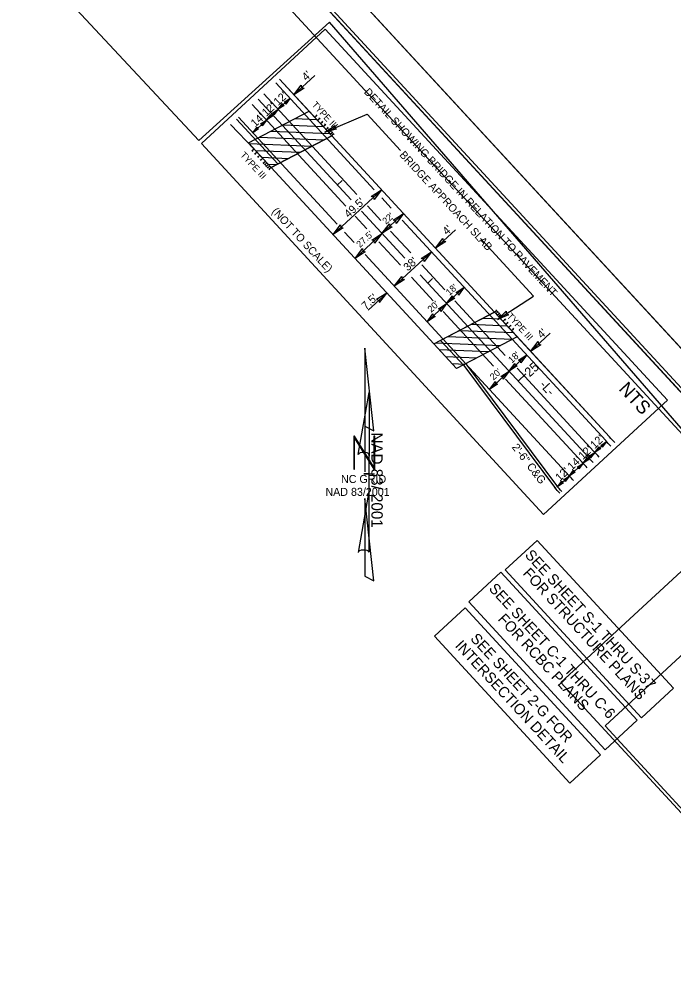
# Model space of a CAD drawing. Extents: x 1702837 to 1704783, y 793612 to 795591.
# Drawn here: x 1703998 to 1704489, y 794195 to 794914 of the extents above; entities that cross this region are included whole.
import ezdxf

# ---------------------------------------------------------------- set-up
doc = ezdxf.new("R2010")
doc.units = 0
for name, color, linetype in [('Default', 7, 'Continuous'), ('Old_Level_1', 7, 'Continuous'), ('Prop Approach Slab', 7, 'Continuous'), ('Prop Conc 2ft 6in Curb and Gutter', 7, 'Continuous'), ('Prop Dimension', 7, 'Continuous'), ('Prop Dimension Text', 7, 'Continuous'), ('Prop EOT', 7, 'Continuous'), ('Prop Guardrail', 7, 'Continuous'), ('Prop Guardrail Anchor Unit CELL', 7, 'Continuous'), ('Prop Horizontal Alignment', 7, 'Continuous'), ('Prop Horizontal Alignment Station Label', 7, 'Continuous'), ('Prop Horizontal Alignment Tick Label', 7, 'Continuous'), ('Prop Horizontal Alignment Tick Large', 7, 'Continuous'), ('Prop Horizontal Alignment Tick Small', 7, 'Continuous'), ('Prop Lane Lines', 7, 'Continuous'), ('Prop North Arrow NAD83 for Plan Sheets CELL', 7, 'Continuous'), ('Prop Paved Shoulder', 7, 'Continuous'), ('Prop Roadway Bridge', 7, 'Continuous'), ('Prop Structure Anchor Unit CELL', 7, 'Continuous'), ('Prop Terminator CELL', 7, 'Continuous'), ('Sheet Clip Boundary CELL', 7, 'Continuous'), ('Sheet Cutting Line CELL', 7, 'Continuous'), ('Sheet Plan CELL', 7, 'Continuous'), ('Sheet Plan Layout CELL', 7, 'Continuous'), ('Sheet Plot Border Inside CELL', 7, 'Continuous'), ('Sheet Plot Border Outside CELL', 7, 'Continuous')]:
    doc.layers.add(name, color=color, linetype=linetype)

# ---------------------------------------------------------------- blocks, each defined once
blk = doc.blocks.new('CTL NORTH ARROW NAD 83 2001')
at = {"layer": 'Default'}
blk.add_line((0, 0), (0, 0), dxfattribs=at)
for points in [[(-0.003, 1.746), (-0.003, 0.579), (0.135, 0.511)], [(-0.168, -0.065), (-0.154, -0.065), (-0.154, 0.401), (0.135, -0.065), (0.148, -0.065), (0.148, 0.428), (0.135, 0.428), (0.135, -0.038), (-0.154, 0.428), (-0.168, 0.428)], [(-0.003, -1.671), (0.135, -1.739), (-0.003, -0.505)]]:
    blk.add_lwpolyline(points, close=True, dxfattribs=at)
blk.add_lwpolyline([(-0.003, 0.579), (-0.003, -0.107)], dxfattribs=at)
for s, p in [('NC GRID', (-0.358, -0.273)), ('NAD 83/2001', (-0.592, -0.466))]:
    blk.add_text(s, height=0.12, dxfattribs=at).set_placement(p)

msp = doc.modelspace()

# ---------------------------------------------------------------- linework, layer by layer
at = {"layer": 'Old_Level_1'}
for p, q in [((1704227.81, 794906.42), (1704134.94, 794820.69)), ((1704484.52, 794628.31), (1704227.81, 794906.42)), ((1704227.47, 794829.28), (1704259.26, 794842.65)), ((1704259.26, 794842.65), (1704284.4, 794815.41)), ((1704384.03, 794706.21), (1704344.17, 794749.39)), ((1704356.92, 794688.74), (1704384.03, 794706.21))]:
    msp.add_line(p, q, dxfattribs=at)
msp.add_lwpolyline([(1704134.94, 794820.69), (1704391.65, 794542.59), (1704484.52, 794628.31)], dxfattribs=at)
for points in [[(1704386.88, 794523.13), (1704489.17, 794412.31), (1704465.13, 794390.13), (1704362.84, 794500.94)], [(1704359.6, 794499.2), (1704461.89, 794388.39), (1704437.85, 794366.2), (1704335.57, 794477.01)], [(1704332.76, 794472.51), (1704434.31, 794362.49), (1704411.24, 794341.2), (1704309.69, 794451.22)]]:
    msp.add_lwpolyline(points, close=True, dxfattribs=at)
at = {"layer": 'Prop Approach Slab'}
for p, q in [((1704170.31, 794821.07), (1704215.71, 794844.86)), ((1704205.15, 794839.32), (1704221.42, 794838.67)), ((1704215.71, 794844.86), (1704232.67, 794826.49)), ((1704196.28, 794834.68), (1704226.22, 794833.48)), ((1704178.53, 794825.38), (1704226.86, 794823.44)), ((1704187.26, 794802.7), (1704232.67, 794826.49)), ((1704187.4, 794830.03), (1704231.02, 794828.28)), ((1704187.26, 794802.7), (1704170.31, 794821.07)), ((1704170.66, 794820.69), (1704217.99, 794818.79)), ((1704175.46, 794815.49), (1704209.11, 794814.15)), ((1704180.25, 794810.3), (1704200.24, 794809.5)), ((1704185.05, 794805.1), (1704191.36, 794804.85)), ((1704354.78, 794694.2), (1704314.38, 794673.1)), ((1704354.75, 794694.23), (1704371.75, 794675.82)), ((1704346.4, 794689.81), (1704359.31, 794689.3)), ((1704328.6, 794680.52), (1704368.9, 794678.91)), ((1704337.5, 794685.17), (1704364.1, 794684.1)), ((1704319.7, 794675.87), (1704368.13, 794673.93)), ((1704371.75, 794675.82), (1704326.29, 794652.09)), ((1704309.33, 794670.47), (1704326.28, 794652.1)), ((1704310.79, 794671.22), (1704359.23, 794669.28)), ((1704313.34, 794666.12), (1704350.32, 794664.64)), ((1704318.14, 794660.92), (1704341.42, 794659.99)), ((1704322.93, 794655.72), (1704332.52, 794655.34))]:
    msp.add_line(p, q, dxfattribs=at)
for points in [[(1704215.71, 794844.86), (1704232.67, 794826.49), (1704187.26, 794802.7), (1704170.31, 794821.07)], [(1704354.75, 794694.23), (1704371.75, 794675.82), (1704326.29, 794652.09), (1704309.33, 794670.46)]]:
    msp.add_lwpolyline(points, close=True, dxfattribs=at)
at = {"layer": 'Prop Conc 2ft 6in Curb and Gutter'}
for p, q in [((1704161.28, 794838.95), (1704192.31, 794805.34)), ((1704314.38, 794673.1), (1704332.07, 794653.94)), ((1704331.8, 794654.26), (1704400.51, 794562.13))]:
    msp.add_line(p, q, dxfattribs=at)
msp.add_arc((1703690.14, 793907.47), 966, 42.36891, 42.70907, dxfattribs=at)
at = {"layer": 'Prop Dimension'}
for p, q in [((1704204.34, 794857.18), (1704220.09, 794871.73)), ((1704192.58, 794846.33), (1704201.4, 794854.47)), ((1704183.76, 794838.19), (1704192.58, 794846.33)), ((1704173.47, 794828.7), (1704183.76, 794838.19)), ((1704233.67, 794752.43), (1704270.04, 794786)), ((1704270.39, 794753.19), (1704286.56, 794768.11)), ((1704250.18, 794734.54), (1704270.39, 794753.19)), ((1704310.51, 794742.16), (1704325.44, 794755.95)), ((1704279.65, 794713.68), (1704307.57, 794739.45)), ((1704274.14, 794708.59), (1704260.16, 794695.69)), ((1704318.91, 794700.63), (1704332.14, 794712.84)), ((1704304.21, 794687.06), (1704318.91, 794700.63)), ((1704381.86, 794664.86), (1704396.54, 794678.4)), ((1704365.7, 794649.94), (1704378.93, 794662.15)), ((1704351, 794636.37), (1704365.7, 794649.94)), ((1704438.85, 794597.24), (1704430.04, 794589.1)), ((1704430.04, 794589.1), (1704421.22, 794580.96)), ((1704421.22, 794580.96), (1704410.92, 794571.46)), ((1704410.92, 794571.46), (1704402.11, 794563.33))]:
    msp.add_line(p, q, dxfattribs=at)
at = {"layer": 'Prop EOT'}
for p, q in [((1704190.68, 794866.08), (1704264.64, 794785.96)), ((1704162.75, 794840.31), (1704236.72, 794760.18)), ((1704270.21, 794779.92), (1704277.41, 794772.13)), ((1704285.63, 794763.22), (1704438.17, 794597.96)), ((1704242.29, 794754.15), (1704249.48, 794746.35)), ((1704257.71, 794737.44), (1704333.54, 794655.29)), ((1704333.4, 794655.45), (1704402.11, 794563.33))]:
    msp.add_line(p, q, dxfattribs=at)
for radius, start in [(1018, 42.38629), (968, 42.36962)]:
    msp.add_arc((1703690.14, 793907.47), radius, start, 42.70907, dxfattribs=at)
at = {"layer": 'Prop Guardrail'}
for p, q in [((1704215.71, 794844.86), (1704193.6, 794868.78)), ((1704156.87, 794834.88), (1704174.55, 794816.48)), ((1704187.26, 794802.7), (1704174.55, 794816.48)), ((1704368.24, 794679.62), (1704354.75, 794694.23)), ((1704441.11, 794600.67), (1704368.24, 794679.62))]:
    msp.add_line(p, q, dxfattribs=at)
msp.add_arc((1703690.01, 793907.39), 1022.16, 42.38713, 42.70735, dxfattribs=at)
at = {"layer": 'Prop Horizontal Alignment'}
for p, q in [((1704177.45, 794853.88), (1704247.18, 794778.34)), ((1704255.02, 794769.84), (1704287.46, 794734.7)), ((1704299.04, 794722.15), (1704424.95, 794585.75))]:
    msp.add_line(p, q, dxfattribs=at)
msp.add_arc((1703690.14, 793907.47), 1000, 42.38048, 42.70907, dxfattribs=at)
at = {"layer": 'Prop Horizontal Alignment Station Label'}
msp.add_circle((1704424.95, 794585.75), 1.5, dxfattribs=at)
at = {"layer": 'Prop Horizontal Alignment Tick Large'}
msp.add_line((1704372.51, 794642.56), (1704378.39, 794647.99), dxfattribs=at)
at = {"layer": 'Prop Horizontal Alignment Tick Small'}
for p, q in [((1704236.85, 794789.52), (1704240.53, 794792.91)), ((1704304.68, 794716.04), (1704308.36, 794719.43))]:
    msp.add_line(p, q, dxfattribs=at)
at = {"layer": 'Prop Lane Lines'}
for p, q in [((1704181.86, 794857.95), (1704251.59, 794782.41)), ((1704173.04, 794849.81), (1704243.25, 794773.74)), ((1704259.43, 794773.91), (1704269.49, 794763.01)), ((1704250.31, 794766.1), (1704258.93, 794756.76)), ((1704276.84, 794755.04), (1704292.01, 794738.62)), ((1704268, 794746.94), (1704284.23, 794729.35)), ((1704300.29, 794729.64), (1704317.56, 794710.94)), ((1704292.52, 794720.37), (1704308.74, 794702.8)), ((1704325.06, 794702.81), (1704362.89, 794661.82)), ((1704316.25, 794694.67), (1704354.07, 794653.68)), ((1704333.02, 794655.85), (1704411.06, 794571.3)), ((1704371.78, 794652.2), (1704429.36, 794589.82)), ((1704362.96, 794644.06), (1704420.54, 794581.68))]:
    msp.add_line(p, q, dxfattribs=at)
for centre, radius, start in [((1703690.14, 793907.47), 1006, 42.38244), ((1703690.14, 793907.47), 994, 42.37849), ((1703690.95, 793906.59), 980, 42.44752)]:
    msp.add_arc(centre, radius, start, 42.70907, dxfattribs=at)
at = {"layer": 'Prop North Arrow NAD83 for Plan Sheets CELL'}
for p, q in [((1704252.55, 794587.64), (1704260.75, 794633.99)), ((1704260.8, 794633.99), (1704260.75, 794633.99)), ((1704260.8, 794633.99), (1704260.75, 794633.99)), ((1704260.8, 794633.99), (1704260.8, 794586.19)), ((1704260.8, 794561.39), (1704260.8, 794587.59)), ((1704260.8, 794586.19), (1704260.8, 794587.54)), ((1704256.8, 794572.99), (1704256.75, 794572.99)), ((1704260.35, 794572.99), (1704256.8, 794572.99)), ((1704256.85, 794572.99), (1704264.85, 794572.99)), ((1704260.8, 794561.39), (1704252.45, 794514.14)), ((1704260.85, 794514.34), (1704260.8, 794561.39))]:
    msp.add_line(p, q, dxfattribs=at)
for centre, start_param, end_param in [((1704256.69, 794587.15), 0.216388, 2.908219), ((1704256.69, 794513.98), 0.201328, 3.141593)]:
    msp.add_ellipse(centre, major_axis=(4.23, -0.03), ratio=0.461098, start_param=start_param, end_param=end_param, dxfattribs=at)
at = {"layer": 'Prop Paved Shoulder'}
for p, q in [((1704193.62, 794868.8), (1704219.95, 794840.26)), ((1704219.95, 794840.26), (1704232.67, 794826.49)), ((1704441.11, 794600.67), (1704371.75, 794675.82))]:
    msp.add_line(p, q, dxfattribs=at)
msp.add_arc((1703690.14, 793907.47), 1022, 42.3888, 42.70907, dxfattribs=at)
at = {"layer": 'Prop Roadway Bridge'}
for p, q in [((1704187.26, 794802.7), (1704232.67, 794826.49)), ((1704232.67, 794826.49), (1704354.75, 794694.23)), ((1704187.26, 794802.7), (1704309.33, 794670.47)), ((1704309.33, 794670.47), (1704354.77, 794694.19))]:
    msp.add_line(p, q, dxfattribs=at)
at = {"layer": 'Prop Structure Anchor Unit CELL'}
for p, q in [((1704219.95, 794840.26), (1704221.42, 794841.62)), ((1704232.67, 794826.49), (1704219.95, 794840.26)), ((1704221.81, 794841.2), (1704221.04, 794842.04)), ((1704222.07, 794837.97), (1704223.54, 794839.32)), ((1704223.93, 794838.9), (1704223.15, 794839.75)), ((1704224.19, 794835.67), (1704225.66, 794837.03)), ((1704226.05, 794836.61), (1704225.27, 794837.45)), ((1704226.31, 794833.38), (1704227.78, 794834.73)), ((1704228.17, 794834.31), (1704227.39, 794835.15)), ((1704228.43, 794831.08), (1704229.9, 794832.44)), ((1704229.49, 794829.93), (1704230.96, 794831.29)), ((1704230.29, 794832.02), (1704229.51, 794832.86)), ((1704231.35, 794830.87), (1704230.57, 794831.71)), ((1704232.41, 794829.72), (1704231.63, 794830.56)), ((1704230.55, 794828.78), (1704232.02, 794830.14)), ((1704231.61, 794827.64), (1704233.08, 794828.99)), ((1704232.67, 794826.49), (1704234.14, 794827.84)), ((1704233.47, 794828.57), (1704232.69, 794829.41)), ((1704234.53, 794827.42), (1704233.75, 794828.26)), ((1704174.55, 794816.48), (1704173.08, 794815.12)), ((1704187.26, 794802.7), (1704174.55, 794816.48)), ((1704173.47, 794814.7), (1704172.69, 794815.54)), ((1704175.58, 794812.4), (1704174.81, 794813.25)), ((1704176.67, 794814.18), (1704175.2, 794812.83)), ((1704177.7, 794810.11), (1704176.93, 794810.95)), ((1704178.79, 794811.89), (1704177.32, 794810.53)), ((1704180.91, 794809.59), (1704179.44, 794808.23)), ((1704179.82, 794807.81), (1704179.05, 794808.65)), ((1704181.94, 794805.52), (1704181.17, 794806.36)), ((1704183.02, 794807.29), (1704181.56, 794805.94)), ((1704183, 794804.37), (1704182.23, 794805.21)), ((1704184.08, 794806.14), (1704182.61, 794804.79)), ((1704184.06, 794803.22), (1704183.29, 794804.06)), ((1704185.14, 794805), (1704183.67, 794803.64)), ((1704185.12, 794802.07), (1704184.35, 794802.91)), ((1704186.2, 794803.85), (1704184.73, 794802.49)), ((1704187.26, 794802.7), (1704185.79, 794801.34)), ((1704186.18, 794800.92), (1704185.41, 794801.76)), ((1704354.75, 794694.23), (1704356.22, 794695.59)), ((1704354.75, 794694.23), (1704367.47, 794680.46)), ((1704355.81, 794693.09), (1704357.28, 794694.44)), ((1704355.83, 794696.01), (1704356.61, 794695.17)), ((1704356.89, 794694.86), (1704357.67, 794694.02)), ((1704356.87, 794691.94), (1704358.34, 794693.29)), ((1704357.93, 794690.79), (1704359.4, 794692.15)), ((1704357.95, 794693.71), (1704358.73, 794692.87)), ((1704358.99, 794689.64), (1704360.46, 794691)), ((1704359.01, 794692.57), (1704359.79, 794691.72)), ((1704360.07, 794691.42), (1704360.85, 794690.58)), ((1704361.11, 794687.34), (1704362.58, 794688.7)), ((1704362.19, 794689.12), (1704362.97, 794688.28)), ((1704364.31, 794686.83), (1704365.09, 794685.98)), ((1704363.23, 794685.05), (1704364.7, 794686.41)), ((1704365.35, 794682.75), (1704366.82, 794684.11)), ((1704366.43, 794684.53), (1704367.21, 794683.69)), ((1704367.47, 794680.46), (1704368.94, 794681.81)), ((1704368.55, 794682.23), (1704369.33, 794681.39))]:
    msp.add_line(p, q, dxfattribs=at)
at = {"layer": 'Prop Terminator CELL'}
for points in [[(1704212, 794862.15), (1704204.34, 794857.18), (1704209.9, 794864.5), (1704210.14, 794862.54)], [(1704196.99, 794851.62), (1704201.4, 794854.47), (1704198.2, 794850.27), (1704198.06, 794851.39)], [(1704188.17, 794843.48), (1704192.58, 794846.33), (1704189.38, 794842.13), (1704189.24, 794843.25)], [(1704196.99, 794849.19), (1704192.58, 794846.33), (1704195.78, 794850.54), (1704195.92, 794849.41)], [(1704179.35, 794835.34), (1704183.76, 794838.19), (1704180.56, 794833.99), (1704180.42, 794835.11)], [(1704188.17, 794841.05), (1704183.76, 794838.19), (1704186.96, 794842.4), (1704187.1, 794841.27)], [(1704177.88, 794831.55), (1704173.47, 794828.7), (1704176.67, 794832.9), (1704176.81, 794831.78)], [(1704236.37, 794831.34), (1704227.47, 794829.28), (1704235.19, 794834.26), (1704234.75, 794832.34)], [(1704262.38, 794781.03), (1704270.04, 794786), (1704264.48, 794778.69), (1704264.24, 794780.64)], [(1704278.89, 794763.14), (1704286.56, 794768.11), (1704280.99, 794760.8), (1704280.75, 794762.75)], [(1704241.34, 794757.39), (1704233.67, 794752.43), (1704239.24, 794759.74), (1704239.48, 794757.78)], [(1704278.06, 794758.15), (1704270.39, 794753.19), (1704275.96, 794760.5), (1704276.2, 794758.55)], [(1704262.73, 794748.22), (1704270.39, 794753.19), (1704264.83, 794745.87), (1704264.59, 794747.83)], [(1704318.17, 794747.13), (1704310.51, 794742.16), (1704316.07, 794749.48), (1704316.31, 794747.52)], [(1704257.85, 794739.5), (1704250.18, 794734.54), (1704255.75, 794741.85), (1704255.99, 794739.89)], [(1704299.9, 794734.48), (1704307.57, 794739.45), (1704302, 794732.14), (1704301.76, 794734.09)], [(1704287.31, 794718.64), (1704279.65, 794713.68), (1704285.21, 794720.99), (1704285.45, 794719.03)], [(1704268.57, 794701.35), (1704274.14, 794708.59), (1704266.4, 794703.63), (1704268.33, 794703.23)], [(1704326, 794708.86), (1704332.14, 794712.84), (1704327.68, 794706.99), (1704327.49, 794708.55)], [(1704325.04, 794704.6), (1704318.91, 794700.63), (1704323.36, 794706.48), (1704323.55, 794704.91)], [(1704312.78, 794696.66), (1704318.91, 794700.63), (1704314.46, 794694.78), (1704314.26, 794696.34)], [(1704365.33, 794692.31), (1704356.92, 794688.74), (1704363.66, 794694.99), (1704363.56, 794693.02)], [(1704310.34, 794691.03), (1704304.21, 794687.06), (1704308.66, 794692.91), (1704308.86, 794691.35)], [(1704389.53, 794669.83), (1704381.86, 794664.86), (1704387.43, 794672.17), (1704387.67, 794670.22)], [(1704372.79, 794658.17), (1704378.93, 794662.15), (1704374.47, 794656.3), (1704374.28, 794657.86)], [(1704371.83, 794653.91), (1704365.7, 794649.94), (1704370.15, 794655.79), (1704370.34, 794654.22)], [(1704359.57, 794645.97), (1704365.7, 794649.94), (1704361.25, 794644.09), (1704361.05, 794645.65)], [(1704357.13, 794640.34), (1704351, 794636.37), (1704355.45, 794642.22), (1704355.65, 794640.66)], [(1704434.45, 794594.38), (1704438.85, 794597.24), (1704435.65, 794593.03), (1704435.52, 794594.16)], [(1704425.63, 794586.25), (1704430.04, 794589.1), (1704426.84, 794584.9), (1704426.7, 794586.02)], [(1704434.44, 794591.96), (1704430.04, 794589.1), (1704433.24, 794593.31), (1704433.37, 794592.18)], [(1704416.81, 794578.11), (1704421.22, 794580.96), (1704418.02, 794576.76), (1704417.88, 794577.88)], [(1704425.62, 794583.82), (1704421.22, 794580.96), (1704424.42, 794585.17), (1704424.56, 794584.04)], [(1704415.33, 794574.31), (1704410.92, 794571.46), (1704414.12, 794575.66), (1704414.26, 794574.54)], [(1704406.52, 794566.18), (1704402.11, 794563.33), (1704405.31, 794567.53), (1704405.45, 794566.41)], [(1704406.52, 794568.6), (1704410.92, 794571.46), (1704407.72, 794567.25), (1704407.58, 794568.38)]]:
    msp.add_lwpolyline(points, close=True, dxfattribs=at)
at = {"layer": 'Sheet Clip Boundary CELL'}
for points in [[(1703013.13, 794728.35), (1703980.58, 793680.27), (1704576.46, 794230.31), (1704404.51, 794416.6), (1704546.5, 794547.66), (1703751.01, 795409.46)], [(1703542.14, 795216.65), (1703013.13, 794728.35), (1703980.58, 793680.27), (1704576.46, 794230.31), (1704404.51, 794416.6), (1704546.5, 794547.66), (1704231.02, 794911.54), (1704133.02, 794823), (1703864.61, 795110.34), (1703672.13, 795335.33)]]:
    msp.add_lwpolyline(points, close=True, dxfattribs=at)
at = {"layer": 'Sheet Cutting Line CELL'}
msp.add_line((1704783.42, 794354.44), (1703641.54, 795591.49), dxfattribs=at)
at = {"layer": 'Sheet Plan CELL'}
for points in [[(1704755.38, 794351.66), (1703737.94, 795453.9), (1702966.4, 794741.71), (1703983.82, 793639.49)], [(1702966.4, 794741.71), (1703737.91, 795453.9), (1704619.69, 794498.69), (1704509.43, 794396.89), (1704645.1, 794249.9), (1703983.82, 793639.49)]]:
    msp.add_lwpolyline(points, close=True, dxfattribs=at)
at = {"layer": 'Sheet Plan Layout CELL'}
for points in [[(1703737.91, 795453.9), (1702966.4, 794741.71), (1703983.81, 793639.5), (1704599.96, 794208.24), (1704437.68, 794384.04), (1704593.08, 794527.49)], [(1704437.68, 794384.04), (1704599.97, 794208.22), (1704755.39, 794351.65), (1704593.08, 794527.49)]]:
    msp.add_lwpolyline(points, close=True, dxfattribs=at)
at = {"layer": 'Sheet Plot Border Inside CELL'}
msp.add_lwpolyline([(1702860.44, 794852.79), (1703990.45, 793628.62), (1704765.67, 794344.18), (1703635.66, 795568.37)], close=True, dxfattribs=at)
at = {"layer": 'Sheet Plot Border Outside CELL'}
msp.add_lwpolyline([(1702836.93, 794848.78), (1703978.81, 793611.73), (1704783.42, 794354.44), (1703641.54, 795591.49)], close=True, dxfattribs=at)

# ---------------------------------------------------------------- block references
at = {"layer": 'Default', "xscale": 50, "yscale": 50}
msp.add_blockref('CTL NORTH ARROW NAD 83 2001', (1704257.58, 794579.81), dxfattribs=at)

# ---------------------------------------------------------------- texts
at = {"layer": 'Old_Level_1'}
for s, height, p in [('DETAIL SHOWING BRIDGE IN RELATION TO PAVEMENT', 5.832, (1704256.51, 794858.96)), ('BRIDGE APPROACH SLAB', 5.832, (1704283.08, 794811.76)), ('(NOT TO SCALE)', 5.832, (1704187.4, 794769.42)), ('NTS', 10, (1704447.42, 794636.24)), (' SEE SHEET S-1 THRU S-37   ', 8, (1704375.1, 794513.96)), ('FOR STRUCTURE PLANS', 8, (1704375.55, 794498.01)), (' SEE SHEET C-1 THRU C-6   ', 8, (1704348.03, 794488.75)), ('FOR RCBC PLANS', 8, (1704356.87, 794463.71)), ('SEE SHEET 2-G FOR  ', 8, (1704336.22, 794449.07)), ('INTERSECTION DETAIL', 8, (1704324.77, 794443.78))]:
    msp.add_text(s, height=height, rotation=312.70907, dxfattribs=at).set_placement(p)
at = {"layer": 'Prop Dimension Text'}
for s, height, rotation, p in [("4'", 6, 42.70907, (1704213.57, 794867.27)), ("12'", 6, 42.70907, (1704192.42, 794848.64)), ("12'", 6, 42.70907, (1704183.62, 794840.52)), ("14'", 6, 42.70907, (1704175.3, 794832.57)), ("49.5'", 6, 42.70907, (1704245.36, 794764.59)), ("22'", 5, 42.70907, (1704273.47, 794759.72)), ("4'", 6, 42.70907, (1704319.07, 794751.62)), ("27.5'", 5, 42.70907, (1704253.89, 794742.27)), ("38'", 6, 42.70907, (1704289.82, 794724.63)), ("18'", 5, 42.70907, (1704321.05, 794706.3)), ("7.5'", 6, 42.70907, (1704258.36, 794695.59)), ("20'", 5, 42.70907, (1704307.31, 794693.62)), ("4'", 6, 42.70907, (1704390.14, 794674.06)), ("18'", 5, 42.70907, (1704367.84, 794655.61)), ("20'", 5, 42.70907, (1704354.1, 794642.93)), ("12'", 6, 42.70907, (1704429.87, 794591.41)), ('2\'-6" C&G', 6, 307.59451, (1704367.47, 794592.91)), ("12'", 6, 42.70907, (1704421.07, 794583.28)), ("14'", 6, 42.70907, (1704412.76, 794575.34)), ("12'", 6, 42.70907, (1704403.73, 794567.01))]:
    msp.add_text(s, height=height, rotation=rotation, dxfattribs=at).set_placement(p)
at = {"layer": 'Prop Guardrail Anchor Unit CELL'}
for p in [(1704217.34, 794849.39), (1704163.68, 794811.71), (1704363.69, 794690.85)]:
    msp.add_text('TYPE III', height=5, rotation=312.73006, dxfattribs=at).set_placement(p)
at = {"layer": 'Prop Horizontal Alignment Tick Label'}
for s, rotation, p in [('25', 42.70907, (1704381.18, 794645.22)), ('-L-', 312.70907, (1704388.07, 794639.35))]:
    msp.add_text(s, height=7, rotation=rotation, dxfattribs=at).set_placement(p)
at = {"layer": 'Prop North Arrow NAD83 for Plan Sheets CELL'}
msp.add_text('NAD 83/ 2001', height=8.5, rotation=270, dxfattribs=at).set_placement((1704262.45, 794604.02))

doc.saveas('drawing.dxf')
